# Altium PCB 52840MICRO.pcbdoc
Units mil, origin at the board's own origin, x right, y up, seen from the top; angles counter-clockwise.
Board outline 1785 x 1570 mil, 2 copper layers (Top Layer, Bottom Layer); 1 components, 0 nets, 81 pads, 0 vias.
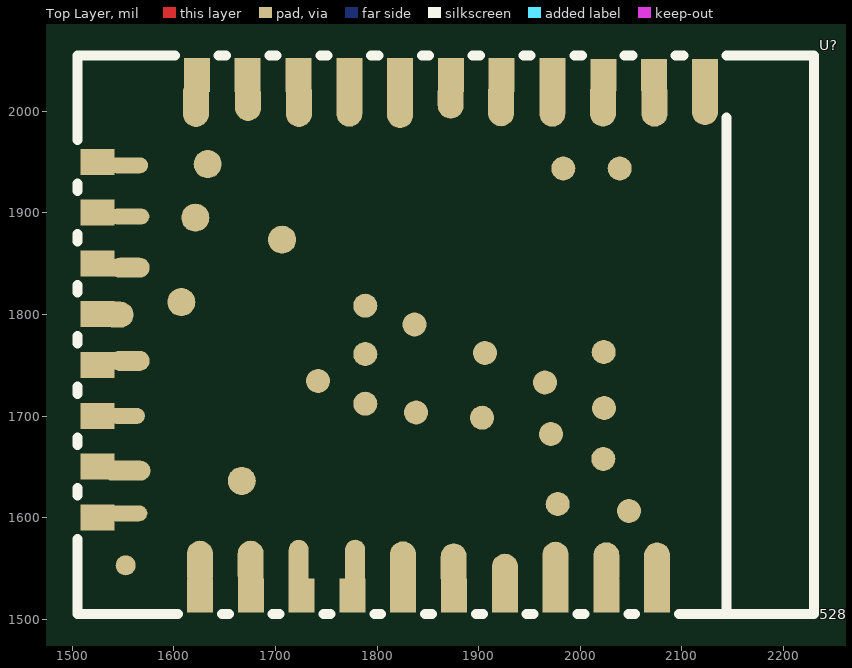
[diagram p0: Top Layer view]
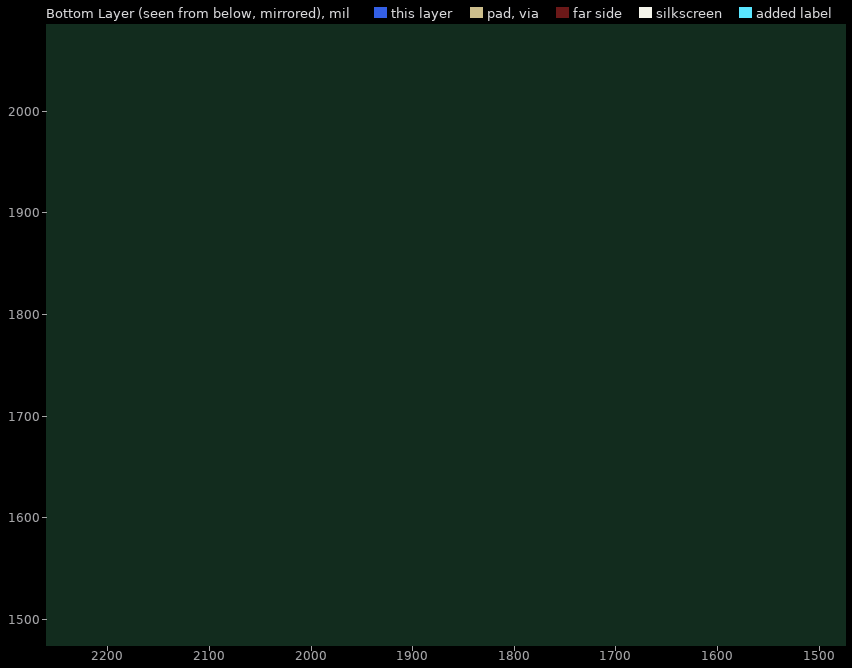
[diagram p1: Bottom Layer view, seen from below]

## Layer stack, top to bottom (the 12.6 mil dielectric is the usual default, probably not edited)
Top Layer: signal copper (thickness not stored)
Dielectric: dielectric 12.6, FR-4, Dk 4.8
Bottom Layer: signal copper (thickness not stored)

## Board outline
2785,1000 1000,1000 1000,2570 2785,2570

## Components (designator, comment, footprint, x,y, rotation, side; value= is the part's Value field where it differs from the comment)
U? "52840MICRO" 52840MICRO 1867.5,1780 r0 top

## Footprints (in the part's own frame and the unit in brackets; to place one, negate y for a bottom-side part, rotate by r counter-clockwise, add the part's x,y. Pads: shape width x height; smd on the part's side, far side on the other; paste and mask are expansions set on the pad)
52840MICRO [mm]
  oval 0.65x1.2 smd paste+0 mask+0.051: 1(5.286,-5.793) 2(4.016,-5.788) 3(2.746,-5.773) 5(0.201,-5.818) 6(-1.069,-5.763) 9(-4.874,-5.748) 10(-6.144,-5.748) 19(-6.244,5.797) 21(-3.669,5.797) 22(-2.409,5.802) 23(-1.139,5.767) 25(1.386,5.812) 26(2.666,5.802) 27(3.931,5.807) 28(5.221,5.802) 29(6.481,5.842)
  rect 0.65x0.85 smd paste+0 mask+0.102: 1(5.287,-6.512) 2(4.017,-6.512) 3(2.747,-6.512) 4(1.477,-6.512) 5(0.207,-6.512) 6(-1.063,-6.512) 7(-2.333,-6.512) 8(-3.603,-6.512) 9(-4.873,-6.512) 10(-6.143,-6.512) 19(-6.22,6.497) 20(-4.95,6.497) 21(-3.68,6.497) 22(-2.41,6.497) 23(-1.14,6.497) 24(0.13,6.497) 25(1.4,6.497) 26(2.67,6.497)
  oval 0.65x0.9 smd paste+0 mask+0.051: 4(1.481,-5.923)
  oval 0.5x1.2 smd paste+0 mask+0.051: 7(-2.264,-5.723) 8(-3.674,-5.728)
  rect 0.85x0.65 smd paste+0 mask+0.102: 11(-8.706,-4.565) 12(-8.706,-3.295) 13(-8.706,-2.025) 14(-8.706,-0.755) 15(-8.706,0.515) 16(-8.706,1.785) 17(-8.706,3.055) 18(-8.706,4.325)
  oval 1x0.4 smd paste+0 mask+0.051: 11(-7.959,-4.463) 17(-7.909,2.957) 18(-7.939,4.237)
  oval 1.2x0.5 smd paste+0 mask+0.051: 12(-7.979,-3.398)
  oval 0.9x0.4 smd paste+0 mask+0.051: 13(-7.969,-2.028)
  oval 1x0.5 smd paste+0 mask+0.051: 14(-7.899,-0.653) 16(-7.899,1.677)
  oval 0.8x0.65 smd paste+0 mask+0.051: 15(-8.204,0.502)
  oval 0.65x1 smd paste+0 mask+0.051: 20(-4.939,5.847) 24(0.126,5.907)
  rect 0.65x0.8 smd paste+0 mask+0.102: 27(3.94,6.497) 28(5.21,6.497) 29(6.48,6.497)
  round 0.6 smd paste+0 mask+0.102: 30(4.351,4.157) 31(2.941,4.157) 32(3.951,-0.433) 33(3.961,-1.833) 34(3.941,-3.103) 35(4.581,-4.403) 36(2.481,-1.193) 37(2.631,-2.483) 38(2.801,-4.233) 39(0.981,-0.453) 40(0.911,-2.073) 41(-0.779,0.257) 42(-0.739,-1.943) 45(-2.009,-1.723)
  round 0.6 smd paste+0 mask+0.1: 43(-2.009,0.727) 44(-2.009,-0.483) 47(-3.189,-1.153)
  round 0.7 smd paste+0 mask+0.1: 46(-4.089,2.378) 51(-5.098,-3.652)
  round 0.7 smd paste+0 mask+0.102: 48(-5.949,4.267) 49(-6.259,2.927) 50(-6.609,0.817)
  round 0.5 smd paste+0 mask+0.102: 52(-7.999,-5.763)
  Mid-Layer 1 pour cut-out: 1.54,-0.216 1.507,2.567 5.473,2.578 6.921,2.54 6.971,-0.493 6.991,-2.613 7.021,-3.503 7.001,-5.733 5.671,-5.173 4.801,-4.273 4.761,-0.213
  Mid-Layer 2 pour cut-out: 5.017,-4.321 4.801,-4.263 4.791,-0.183 1.54,-0.216 1.605,2.605 5.64,2.589 6.921,2.54 6.941,-0.243 4.821,-0.193 4.851,-4.203 5.017,-4.321
  Mid-Layer 2 pour cut-out: 7.011,-5.743 6.071,-4.603 5.017,-4.321 6.061,-4.603 7.011,-5.743
  silkscreen extent -9.21,-6.98 9.21,6.98

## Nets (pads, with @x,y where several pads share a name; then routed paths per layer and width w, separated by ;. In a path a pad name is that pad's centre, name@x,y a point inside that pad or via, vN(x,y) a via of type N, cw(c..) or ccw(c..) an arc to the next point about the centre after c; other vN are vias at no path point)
pads on no net: U?.1 U?.2 U?.3 U?.4 U?.5 U?.6 U?.7 U?.8 U?.9 U?.10 U?.11 U?.12 U?.13 U?.14 U?.15 U?.16 U?.17 U?.18 U?.19 U?.20 U?.21 U?.22 U?.23 U?.24 U?.25 U?.26 U?.27 U?.28 U?.29 U?.30 U?.31 U?.32 U?.33 U?.34 U?.35 U?.36 U?.37 U?.38 U?.39 U?.40 U?.41 U?.42 U?.43 U?.44 U?.45 U?.46 U?.47 U?.48 U?.49 U?.50 U?.51 U?.52

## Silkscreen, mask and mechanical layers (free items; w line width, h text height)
Document:
  lines w0.1: 1892.49,1784.99 1892.51,1785.01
